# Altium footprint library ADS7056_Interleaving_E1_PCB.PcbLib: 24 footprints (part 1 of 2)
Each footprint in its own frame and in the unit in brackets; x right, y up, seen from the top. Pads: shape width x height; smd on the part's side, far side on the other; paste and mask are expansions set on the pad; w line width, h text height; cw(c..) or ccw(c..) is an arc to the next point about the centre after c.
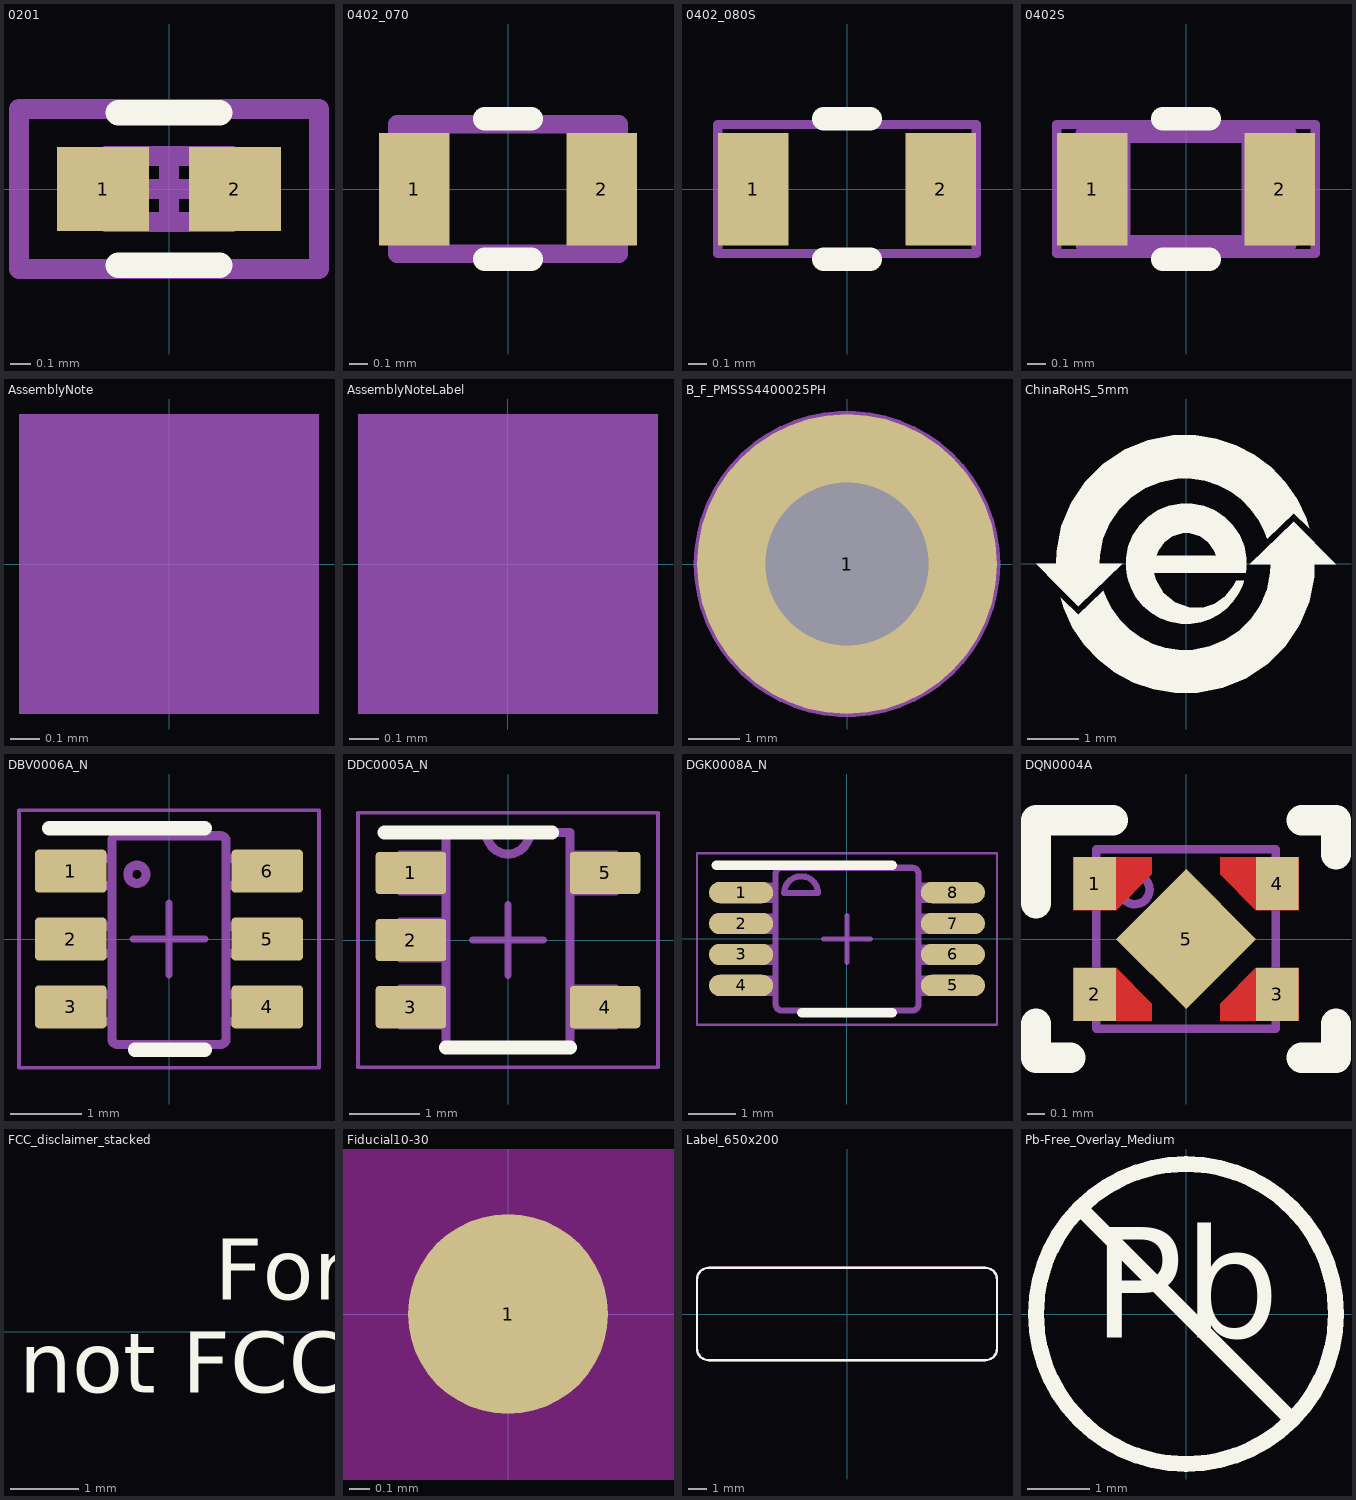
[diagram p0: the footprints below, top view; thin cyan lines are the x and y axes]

## 0201 [mm] "Data from Kemet datasheet CC101_COM dated 7/28/11"
height 0.26
pads (2):
  rect 0.46x0.42 smd mask+0.048: 1(-0.33,0) 2(0.33,0)
Top Overlay:
  lines w0.127: -0.254,-0.381 0.254,-0.381 ; -0.254,0.381 0.254,0.381
Mechanical 5:
  lines w0.1: -0.75,-0.4 -0.75,0.4 0.75,0.4 0.75,-0.4 -0.75,-0.4
  text ".Designator" at -0.66,-0.178 h0.36
Mechanical 13:
  lines w0.1: -0.215,-0.165 -0.215,0.165 ; 0.215,-0.165 0.215,0.165 ; -0.315,-0.165 0.315,-0.165 0.315,0.165 -0.315,0.165 -0.315,-0.165
Mechanical 15:
  lines w0.1: -0.165,0 0.165,0 ; 0,-0.165 0,0.165 ; -0.75,-0.4 0.75,-0.4 0.75,0.4 -0.75,0.4 -0.75,-0.4
3D body: height 0.26, standoff 0, extent 0.216,-0.164 0.314,0.164
3D body: height 0.26, standoff 0, extent -0.214,-0.164 0.214,0.164
3D body: height 0.26, standoff 0, extent -0.314,-0.164 -0.216,0.164

## 0402_070 [mil] "SMD, 2-Leads, Body 1.2x0.7mm, Height 0.7mm"
height 27.56
pads (2):
  rect 15x24 smd: 1(-20,0) 2(20,0)
Top Overlay:
  lines w5: -5,-15 5,-15 ; -5,15 5,15
Mechanical 5:
  lines w3.94: -23.62,-13.78 23.62,-13.78 23.62,13.78 -23.62,13.78 -23.62,-13.78
  text ".Designator" at -21.65,-5.91 h12
3D body: height 27.56, standoff 0, extent -13.78,-13.78 13.78,13.78
3D body: height 27.56, standoff 0, extent -23.62,-13.78 -13.78,13.78
3D body: height 27.56, standoff 0, extent 13.78,-13.78 23.62,13.78

## 0402_080S [mil] "Based on C0402S footprint from PADS legacy"
height 31.5
pads (2):
  rect 15x24 smd: 1(-20,0) 2(20,0)
Top Overlay:
  lines w5: -5,-15 5,-15 ; -5,15 5,15
Mechanical 5:
  lines w1.97: -27.56,-13.78 27.56,-13.78 27.56,13.78 -27.56,13.78 -27.56,-13.78
  text ".Designator" at -21.65,-5.91 h12
3D body: height 31.5, standoff 0, extent 12.62,-15.72 25.57,15.73
3D body: height 31.5, standoff 0, extent -12.58,-15.72 12.58,15.73
3D body: height 31.5, standoff 0, extent -25.57,-15.72 -12.62,15.73

## 0402S [mil] "Based on C0402S footprint from PADS legacy"
height 23.62
pads (2):
  rect 15x24 smd: 1(-20,0) 2(20,0)
Top Overlay:
  lines w5: -5,-15 5,-15 ; -5,15 5,15
Mechanical 5:
  lines w1.97: -27.56,-13.78 27.56,-13.78 27.56,13.78 -27.56,13.78 -27.56,-13.78
  text ".Designator" at -21.65,-5.91 h12
Mechanical 13:
  lines w3.94: -13.78,-11.81 -13.78,11.81 ; 13.78,-11.81 13.78,11.81 ; -21.65,-11.81 -21.65,11.81 21.65,11.81 21.65,-11.81 -21.65,-11.81
3D body: height 23.62, standoff 0, extent -21.63,-11.79 -13.8,11.79
3D body: height 23.62, standoff 0, extent -13.76,-11.79 13.76,11.79
3D body: height 23.62, standoff 0, extent 13.8,-11.79 21.63,11.79

## AssemblyNote [mm] "Assembly Note"
Mechanical 5:
  rectangle: -0.508,-0.508 0.508,0.508
  text ".Comment" at 1.143,-0.508 h1.02
  text ".Designator" at -4.191,-0.508 h1.02

## AssemblyNoteLabel [mm] "Assembly Note for PCB Labels"
Mechanical 5:
  rectangle: -0.508,-0.508 0.508,0.508
  text "Install label in silkscreened box after final wash.  Text shall be 8 pt font.  Text shall be per the Label Table in the PDF schematic." at 1.143,-0.508 h1.02
  text ".Designator" at -4.191,-0.508 h1.02

## B_F_PMSSS4400025PH [mil] "MACHINE SCREW PAN PHILLIPS 4-40"
height 82.68
pads (1):
  round 230 hole 125: 1(0,0)
Mechanical 5:
  circle w5: c0,0 r115
  text ".Designator" at 150,-15 h40
3D body "PMSSS 440 0025 PH.stp": height 79.21, standoff -248.03, extent -109.49,-109.49 109.51,109.51

## ChinaRoHS_5mm [mm] "Minimum height for China RoHS symbol"
Top Overlay:
  drawing of 5 lines, arcs and shapes, not listed

## DBV0006A_N [mm] "SOT23, 6-Leads, Body 2.9x1.6mm, Pitch 0.95mm, Lead Span 2.8mm, IPC Medium Density"
height 1.45
pads (6):
  rrect17% 1x0.6 smd: 1(-1.375,0.95) 2(-1.375,0) 3(-1.375,-0.95) 4(1.375,-0.95) 5(1.375,0) 6(1.375,0.95)
Top Overlay:
  lines w0.2: -1.675,1.55 0.5,1.55 ; -0.475,-1.55 0.5,-1.55
Mechanical 5:
  lines w0.127: 0.724,-1.475 ccw(c0.723,-1.399) 0.8,-1.399 0.8,1.37 ccw(c0.723,1.37) 0.724,1.446 ; 0.723,-1.475 -0.724,-1.475 -0.725,-1.475 cw(c-0.724,-1.399) -0.801,-1.399 -0.801,1.37 cw(c-0.724,1.37) -0.725,1.446 -0.724,1.446 0.723,1.446 ; 0.723,-1.475 0.724,-1.475 ; 0.723,1.446 0.724,1.446 ; -1.423,-1.154 -1.423,-0.78 -1.206,-0.78 -1.113,-0.78 -1.081,-0.78 -0.828,-0.78 -0.801,-0.78 -0.801,-1.154 -0.828,-1.154 -1.081,-1.154 -1.113,-1.154 -1.206,-1.154 -1.423,-1.154 ; -1.423,-0.202 -1.423,0.173 -1.206,0.173 -1.113,0.173 -1.081,0.173 -0.828,0.173 -0.801,0.173 -0.801,-0.202 -0.828,-0.202 -1.081,-0.202 -1.113,-0.202 -1.206,-0.202 -1.423,-0.202 ; -1.423,0.751 -1.423,1.125 -1.206,1.125 -1.113,1.125 -1.081,1.125 -0.828,1.125 -0.801,1.125 -0.801,0.751 -0.828,0.751 -1.081,0.751 -1.113,0.751 -1.206,0.751 -1.423,0.751 ; -0.577,0.906 ccw(c-0.45,0.906) -0.323,0.906 ccw(c-0.45,0.906) -0.577,0.906 ; 0.8,-1.154 0.8,-0.78 0.827,-0.78 1.08,-0.78 1.112,-0.78 1.205,-0.78 1.422,-0.78 1.422,-1.154 1.205,-1.154 1.112,-1.154 1.08,-1.154 0.827,-1.154 0.8,-1.154 ; 0.8,-0.202 0.8,0.173 0.827,0.173 1.08,0.173 1.112,0.173 1.205,0.173 1.422,0.173 1.422,-0.202 1.205,-0.202 1.112,-0.202 1.08,-0.202 0.827,-0.202 0.8,-0.202 ; 0.8,0.751 0.8,1.125 0.827,1.125 1.08,1.125 1.112,1.125 1.205,1.125 1.422,1.125 1.422,0.751 1.205,0.751 1.112,0.751 1.08,0.751 0.827,0.751 0.8,0.751
  text ".Designator" at -0.075,0.925 h0.51
Mechanical 15:
  lines w0.05: -2.1,-1.8 -2.1,1.8 2.1,1.8 2.1,-1.8 -2.1,-1.8
  lines w0.1: -0.5,0 0.5,0 ; 0,-0.5 0,0.5
3D body "DBV0006A.stp": height 1.12, standoff 0, extent -1.422,-1.461 1.423,1.46

## DDC0005A_N [mm]
height 1.1
pads (5):
  rrect17% 1x0.6 smd: 1(-1.375,0.95) 2(-1.375,0) 3(-1.375,-0.95) 4(1.375,-0.95) 5(1.375,0.95)
Top Overlay:
  lines w0.2: -1.75,1.525 0.625,1.525 ; -0.876,-1.524 0.876,-1.524
Mechanical 5:
  lines w0.127: -0.305,1.524 ccw(c0,1.524) 0.305,1.524 ; -1.524,-1.204 -0.876,-1.204 -0.876,-0.696 -1.524,-0.696 -1.524,-1.204 ; -1.524,-0.254 -0.876,-0.254 -0.876,0.254 -1.524,0.254 -1.524,-0.254 ; -1.524,0.696 -0.876,0.696 -0.876,1.204 -1.524,1.204 -1.524,0.696 ; -0.876,-1.524 -0.876,1.524 0.876,1.524 0.876,-1.524 -0.876,-1.524 ; 0.876,-1.204 1.524,-1.204 1.524,-0.696 0.876,-0.696 0.876,-1.204 ; 0.876,0.696 1.524,0.696 1.524,1.204 0.876,1.204 0.876,0.696
  text ".Designator" at -0.35,1.075 h0.6
Mechanical 15:
  lines w0.05: -2.125,-1.8 -2.125,1.8 2.125,1.8 2.125,-1.8 -2.125,-1.8
  lines w0.1: -0.5,0 0.5,0 ; 0,-0.5 0,0.5
3D body "DDC0005A.stp": height 1.1, standoff 0, extent -1.405,-1.45 1.406,1.45

## DGK0008A_N [mm] "TSOP, 8-Leads, Body 3x3mm, Pitch 0.65mm, IPC Medium Density"
height 1.1
pads (8):
  oval 1.35x0.45 smd: 1(-2.225,0.975) 2(-2.225,0.325) 3(-2.225,-0.325) 4(-2.225,-0.975) 5(2.225,-0.975) 6(2.225,-0.325) 7(2.225,0.325) 8(2.225,0.975)
Top Overlay:
  lines w0.2: -2.75,1.55 0.95,1.55 ; -0.95,-1.55 0.95,-1.55
Mechanical 5:
  lines w0.127: -2.45,-1.131 -2.45,-0.826 -2.21,-0.826 -2.091,-0.826 -2.087,-0.826 -1.784,-0.826 -1.498,-0.826 -1.498,-1.131 -1.784,-1.131 -2.087,-1.131 -2.091,-1.131 -2.21,-1.131 -2.45,-1.131 ; -2.45,-0.48 -2.45,-0.175 -2.21,-0.175 -2.091,-0.175 -2.087,-0.175 -1.784,-0.175 -1.498,-0.175 -1.498,-0.48 -1.784,-0.48 -2.087,-0.48 -2.091,-0.48 -2.21,-0.48 -2.45,-0.48 ; -2.45,0.17 -2.45,0.475 -2.21,0.475 -2.091,0.475 -2.087,0.475 -1.784,0.475 -1.498,0.475 -1.498,0.17 -1.784,0.17 -2.087,0.17 -2.091,0.17 -2.21,0.17 -2.45,0.17 ; -2.45,0.82 -2.45,1.125 -2.21,1.125 -2.091,1.125 -2.087,1.125 -1.784,1.125 -1.498,1.125 -1.498,0.82 -1.784,0.82 -2.087,0.82 -2.091,0.82 -2.21,0.82 -2.45,0.82 ; -1.497,-1.377 ccw(c-1.37,-1.374) -1.373,-1.501 -1.371,-1.501 1.373,-1.501 1.375,-1.501 ccw(c1.373,-1.374) 1.5,-1.377 1.5,-1.374 1.5,1.369 1.5,1.372 ccw(c1.373,1.369) 1.375,1.496 1.373,1.496 -1.371,1.496 -1.373,1.496 ccw(c-1.37,1.369) -1.497,1.372 -1.498,1.369 -1.498,-1.374 -1.497,-1.377 ; -1.32,0.962 cw(c-0.964,0.962) -0.609,0.962 -1.32,0.962 ; 1.5,-1.131 1.786,-1.131 2.089,-1.131 2.093,-1.131 2.213,-1.131 2.452,-1.131 2.452,-0.826 2.213,-0.826 2.093,-0.826 2.089,-0.826 1.786,-0.826 1.5,-0.826 1.5,-1.131 ; 1.5,-0.48 1.786,-0.48 2.089,-0.48 2.093,-0.48 2.213,-0.48 2.452,-0.48 2.452,-0.175 2.213,-0.175 2.093,-0.175 2.089,-0.175 1.786,-0.175 1.5,-0.175 1.5,-0.48 ; 1.5,0.17 1.786,0.17 2.089,0.17 2.093,0.17 2.213,0.17 2.452,0.17 2.452,0.475 2.213,0.475 2.093,0.475 2.089,0.475 1.786,0.475 1.5,0.475 1.5,0.17 ; 1.5,0.82 1.786,0.82 2.089,0.82 2.093,0.82 2.213,0.82 2.452,0.82 2.452,1.125 2.213,1.125 2.093,1.125 2.089,1.125 1.786,1.125 1.5,1.125 1.5,0.82
  text ".Designator" at -1.15,-0.3 h0.64
Mechanical 15:
  lines w0.05: -3.15,-1.8 -3.15,1.8 3.15,1.8 3.15,-1.8 -3.15,-1.8
  lines w0.1: -0.5,0 0.5,0 ; 0,-0.5 0,0.5
3D body "DGK0008A.stp": height 0.96, standoff 0, extent -2.451,-1.499 2.451,1.499

## DQN0004A [mm] "SON, 0.65mm pitch"
height 0.4
pads (5):
  rect 0.25x0.31 smd paste-1 mask-0.31: 1(-0.535,0.325) 2(-0.535,-0.325) 3(0.535,-0.325) 4(0.535,0.325)
  rect 0.58x0.58 smd rot 45 paste-0.065 mask-0.05: 5(0,0)
Top Layer:
  region: -0.66,-0.48 -0.2,-0.48 -0.2,-0.379 -0.409,-0.17 -0.66,-0.17
  region: 0.66,-0.48 0.2,-0.48 0.2,-0.379 0.409,-0.17 0.66,-0.17
  region: 0.66,0.48 0.2,0.48 0.2,0.379 0.409,0.17 0.66,0.17
  region: -0.66,0.48 -0.2,0.48 -0.2,0.379 -0.409,0.17 -0.66,0.17
Top Overlay:
  lines w0.178: -0.88,-0.496 -0.88,-0.696 -0.68,-0.696 ; -0.88,0.21 -0.88,0.696 -0.43,0.696 ; 0.68,-0.696 0.88,-0.696 0.88,-0.496 ; 0.68,0.696 0.88,0.696 0.88,0.496
Top Paste:
  region: -0.65,0.43 -0.25,0.43 -0.25,0.4 -0.43,0.22 -0.65,0.22
  region: 0.65,0.43 0.25,0.43 0.25,0.4 0.43,0.22 0.65,0.22
  region: 0.65,-0.43 0.25,-0.43 0.25,-0.4 0.43,-0.22 0.65,-0.22
  region: -0.65,-0.43 -0.25,-0.43 -0.25,-0.4 -0.43,-0.22 -0.65,-0.22
Mechanical 5:
  circle w0.05: c-0.3,0.29 r0.086
  lines w0.05: -0.525,-0.525 0.525,-0.525 0.525,0.525 -0.525,0.525 -0.525,-0.525
  text ".Designator" at -0.43,-0.14 h0.2
3D body: height 0.42, standoff 0.2, extent -0.386,0.204 -0.214,0.376
3D body: height 0.4, standoff 0, extent -0.525,-0.525 0.525,0.525

## FCC_disclaimer_stacked [mm]
Top Overlay:
  text "not FCC approved for resale." at -8.688,-1.178 h1.52
  text "For evaluation only;" at -5.834,0.178 h1.52

## Fiducial10-30 [mm]
pads (1):
  round 1 smd mask+1: 1(0,0)
Top Layer keep-out:
  circle w1.678: c0,0 r0.75

## Label_650x200 [mm] "Thermal Transfer Label"
height 0.025
Top Overlay:
  lines w0.127: -8.255,-1.905 ccw(c-7.62,-1.905) -7.62,-2.54 7.62,-2.54 ccw(c7.62,-1.905) 8.255,-1.905 8.255,1.905 ccw(c7.62,1.905) 7.62,2.54 -7.62,2.54 ccw(c-7.62,1.905) -8.255,1.905 -8.255,-1.905
Mechanical 5:
  lines w0.127: -8.255,-1.905 ccw(c-7.62,-1.905) -7.62,-2.54 7.62,-2.54 ccw(c7.62,-1.905) 8.255,-1.905 8.255,1.905 ccw(c7.62,1.905) 7.62,2.54 -7.62,2.54 ccw(c-7.62,1.905) -8.255,1.905 -8.255,-1.905
  text ".Designator" at -1.524,-0.508 h1.02
3D body: height 0.03, standoff 0, extent -8.256,-2.541 8.256,2.541

## Pb-Free_Overlay_Medium [mm]
Top Overlay:
  circle w0.254: c0,0 r2.413
  lines w0.254: -1.706,1.706 1.706,-1.706
  text "Pb" at -1.505,-0.961 h3.05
